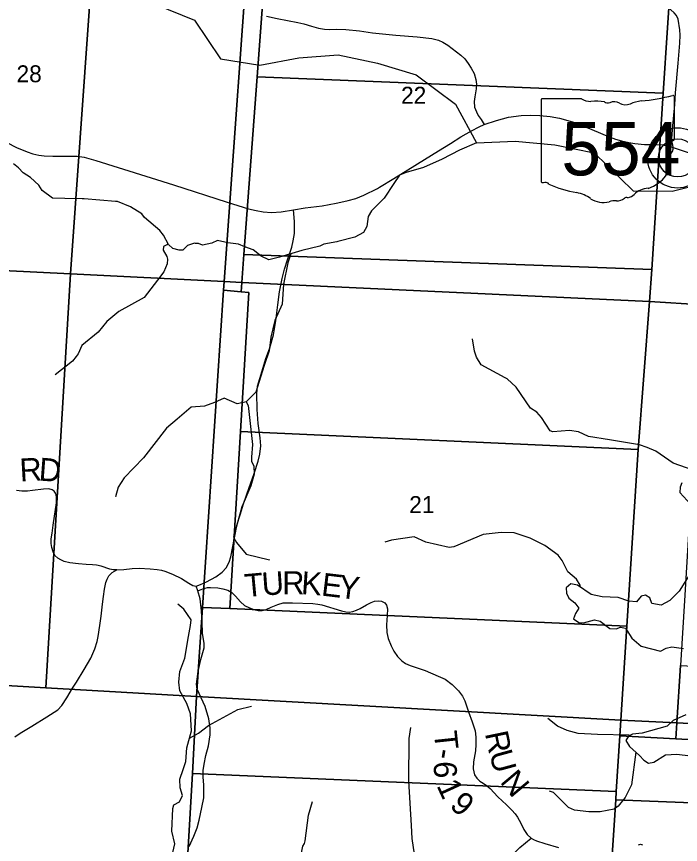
# Model space of a CAD drawing. Extents: x 1878108 to 2183446, y 146837 to 508383.
# Drawn here: x 2057947 to 2066610, y 348659 to 359472 of the extents above; entities that cross this region are included whole.
import ezdxf

# ---------------------------------------------------------------- set-up
doc = ezdxf.new("R2010")
doc.units = 0
for name, color, linetype in [('GM_X_County_Road', 7, 'Continuous'), ('GM_X_County_Road_Text', 7, 'Continuous'), ('GM_X_Major_Lake', 7, 'Continuous'), ('GM_X_Minor_River', 7, 'Continuous'), ('GM_X_Section', 7, 'Continuous'), ('GM_X_Section_Text', 7, 'Continuous'), ('GM_X_State_Location', 7, 'Continuous'), ('GM_X_State_Route', 7, 'Continuous'), ('GM_X_State_Shield', 7, 'Continuous'), ('GM_X_Township_Road', 7, 'Continuous'), ('GM_X_Township_Road_Text', 7, 'Continuous'), ('GM_X_Unincorporated', 7, 'Continuous'), ('GM_X_Unincorporated_Location', 7, 'Continuous')]:
    doc.layers.add(name, color=color, linetype=linetype)

msp = doc.modelspace()

# ---------------------------------------------------------------- linework, layer by layer
at = {"layer": 'GM_X_County_Road'}
for points in [[(2061207, 359477), (2061347, 359447), (2061616, 359395), (2061694, 359378), (2061798, 359348), (2061886, 359322), (2061965, 359307), (2062026, 359301), (2062127, 359306), (2062245, 359305), (2062423, 359287), (2062593, 359260), (2062898, 359231), (2063176, 359207), (2063366, 359184), (2063455, 359163), (2063508, 359138), (2063576, 359097), (2063744, 358966), (2063797, 358919), (2063841, 358861), (2063881, 358798), (2063917, 358727), (2063941, 358651), (2063948, 358590), (2063944, 358530), (2063939, 358500)], [(2063939, 358500), (2063927, 358422), (2063920, 358362), (2063925, 358289), (2063947, 358228), (2063970, 358181), (2064009, 358127), (2064051, 358062)], [(2060289, 352033), (2060349, 352056), (2060426, 352091), (2060548, 352155), (2060632, 352217), (2060683, 352274), (2060720, 352344), (2060745, 352417), (2060790, 352662), (2060824, 352842), (2060863, 352965), (2060910, 353106), (2060981, 353320), (2061046, 353506), (2061098, 353665), (2061122, 353758), (2061133, 353864), (2061126, 353968), (2061100, 354158), (2061087, 354338), (2061083, 354549), (2061090, 354645), (2061150, 354846), (2061201, 355007), (2061254, 355144), (2061300, 355317), (2061331, 355496), (2061355, 355705), (2061380, 355875), (2061414, 356051), (2061444, 356175), (2061487, 356310), (2061540, 356460), (2061558, 356543), (2061572, 356637), (2061573, 356796), (2061562, 356946)], [(2059257, 352245), (2059209, 352247), (2059162, 352254), (2059052, 352293), (2058991, 352307), (2058940, 352312), (2058855, 352315), (2058755, 352324), (2058640, 352339), (2058570, 352353), (2058524, 352376), (2058485, 352398), (2058448, 352434), (2058423, 352481), (2058406, 352538), (2058400, 352589), (2058398, 352652), (2058410, 352725), (2058425, 352829), (2058468, 353122), (2058468, 353195), (2058463, 353224), (2058455, 353249), (2058437, 353274), (2058413, 353292), (2058368, 353304), (2058297, 353299), (2058157, 353280), (2058088, 353274), (2058014, 353275), (2057945, 353281)], [(2057926, 350067), (2057992, 350112), (2058146, 350203), (2058340, 350324), (2058486, 350419), (2058538, 350472), (2058603, 350576), (2058677, 350699), (2058727, 350781), (2058828, 350945), (2058915, 351091), (2058969, 351214), (2058998, 351310), (2059011, 351377), (2059034, 351519), (2059050, 351643), (2059068, 351797), (2059082, 351896), (2059095, 351994), (2059112, 352082), (2059128, 352125), (2059150, 352167), (2059195, 352212), (2059257, 352245), (2059346, 352252), (2059455, 352265), (2059548, 352266), (2059690, 352259), (2059782, 352249), (2059838, 352241), (2059880, 352230), (2059981, 352191), (2060101, 352132), (2060197, 352072), (2060249, 352042), (2060289, 352033)], [(2060198, 348631), (2060260, 348767), (2060302, 348875), (2060330, 348978), (2060364, 349141), (2060389, 349267), (2060392, 349346), (2060391, 349434), (2060381, 349543), (2060380, 349627), (2060395, 349708), (2060417, 349819), (2060451, 349946), (2060473, 350091), (2060475, 350184), (2060456, 350298), (2060408, 350460), (2060356, 350576), (2060302, 350689), (2060295, 350752), (2060317, 350917), (2060351, 351076), (2060395, 351227), (2060397, 351286), (2060375, 351420), (2060371, 351568), (2060359, 351711), (2060344, 351869), (2060311, 351970), (2060289, 352033)]]:
    msp.add_lwpolyline(points, dxfattribs=at)
at = {"layer": 'GM_X_Major_Lake'}
for points in [[(2066628, 353383), (2066605, 353326), (2066602, 353256), (2066794, 353045)], [(2066778, 352260), (2066594, 351968), (2066474, 351846), (2066361, 351786), (2066236, 351806), (2066209, 351881), (2066154, 351915), (2066100, 351902), (2066035, 351830), (2065935, 351835), (2065799, 351883), (2065587, 351893), (2065444, 351923), (2065269, 352045), (2065181, 352065), (2065119, 352010), (2065124, 351940), (2065156, 351878), (2065233, 351815), (2065286, 351746), (2065239, 351675), (2065216, 351606), (2065285, 351559), (2065345, 351554), (2065491, 351595), (2065564, 351574), (2065691, 351480), (2065772, 351477), (2065826, 351496), (2065894, 351483), (2065978, 351354), (2066098, 351248), (2066352, 351182), (2066422, 351223), (2066498, 351240), (2066649, 351219)], [(2066193, 349719), (2066263, 349736), (2066414, 349830), (2066562, 349837), (2066741, 349816), (2066795, 349839), (2066873, 349970), (2066810, 350017), (2066744, 350038), (2066771, 350097), (2066980, 350165), (2067119, 350177), (2067178, 350202), (2067405, 350477)], [(2066681, 350352), (2066515, 350279), (2066438, 350206), (2066111, 350112), (2065984, 350098), (2065931, 350073), (2065899, 350019), (2065945, 349937), (2066075, 349823), (2066132, 349758), (2066193, 349719)]]:
    msp.add_lwpolyline(points, dxfattribs=at)
at = {"layer": 'GM_X_Minor_River'}
for points in [[(2059764, 359629), (2060267, 359426), (2060609, 358922), (2061120, 358838), (2061630, 358931), (2062144, 358971), (2062658, 358865), (2063161, 358712), (2063677, 358329), (2063951, 357825), (2064452, 357843), (2064970, 357798), (2065483, 357694), (2065993, 357194), (2066503, 357190), (2067005, 357320)], [(2063951, 357825), (2063727, 357726), (2063500, 357611), (2063257, 357500), (2063033, 357436), (2062944, 357400), (2062870, 357291), (2062745, 357100), (2062579, 356933), (2062535, 356861), (2062520, 356730), (2062474, 356650), (2062363, 356589), (2062139, 356534), (2062125, 356530), (2061956, 356501), (2061906, 356475), (2061668, 356416), (2061377, 356328), (2061238, 356295), (2061139, 356343), (2061035, 356426), (2060927, 356464), (2060845, 356500), (2060705, 356519), (2060567, 356546), (2060496, 356512), (2060372, 356485), (2060322, 356509), (2060284, 356509), (2060268, 356511), (2060176, 356484), (2060116, 356420), (2060069, 356420), (2059985, 356441), (2059928, 356497), (2059864, 356619), (2059818, 356679), (2059615, 356846), (2059581, 356894), (2059433, 356986), (2059266, 357057), (2059239, 357055), (2058831, 357091), (2058803, 357091), (2058579, 357094), (2058415, 357101), (2058283, 357199), (2058239, 357269), (2058127, 357370), (2058034, 357430), (2057972, 357498), (2057908, 357548)], [(2059923, 356507), (2059910, 356489), (2059866, 356471), (2059860, 356423), (2059908, 356340), (2059918, 356302), (2059911, 356242), (2059867, 356140), (2059786, 356030), (2059613, 355805), (2059280, 355622), (2059125, 355488), (2059014, 355348), (2058799, 355176), (2058749, 355066), (2058726, 355034), (2058676, 354972), (2058449, 354792)], [(2061528, 356373), (2061488, 356257), (2061431, 355978), (2061412, 355717), (2061316, 355502), (2061263, 355286), (2061245, 355107), (2061178, 354913), (2061070, 354568), (2060945, 354442), (2060969, 354391), (2061025, 353883), (2061013, 353716), (2061012, 353664), (2061044, 353600), (2061046, 353495), (2061005, 353345), (2060902, 353108), (2060888, 353070), (2060780, 352673), (2060818, 352603), (2060945, 352452), (2061249, 352376), (2061249, 352382)], [(2066776, 353548), (2066517, 353639), (2066291, 353795), (2066177, 353844), (2066075, 353878), (2065683, 353944), (2065409, 353986), (2065281, 354050), (2065161, 354067), (2064944, 354050), (2064910, 354060), (2064799, 354237), (2064737, 354306), (2064655, 354359), (2064468, 354633), (2064350, 354742), (2064324, 354754), (2064012, 354922), (2063949, 355025), (2063923, 355103), (2063898, 355262)], [(2060947, 354439), (2060825, 354414), (2060657, 354487), (2060529, 354430), (2060400, 354384), (2060226, 354369), (2060041, 354213), (2059904, 354095), (2059602, 353707), (2059351, 353447), (2059274, 353325), (2059240, 353200), (2059238, 353199)], [(2065308, 352018), (2065303, 352044), (2065252, 352126), (2065141, 352219), (2065069, 352370), (2065016, 352438), (2064840, 352562), (2064649, 352658), (2064440, 352728), (2064269, 352734), (2064035, 352707), (2063654, 352547), (2063594, 352536), (2063287, 352606), (2063134, 352677), (2062838, 352635), (2062752, 352608)], [(2059985, 348554), (2060012, 348666), (2059972, 348831), (2059988, 349130), (2060000, 349175), (2060074, 349218), (2060113, 349297), (2060081, 349399), (2060077, 349512), (2060120, 349638), (2060157, 349744), (2060169, 349923), (2060230, 350145), (2060215, 350366), (2060168, 350501), (2060076, 350664), (2060063, 350781), (2060077, 350919), (2060142, 351092), (2060191, 351377), (2060218, 351517), (2060224, 351591), (2060129, 351732), (2060051, 351796)], [(2060203, 350046), (2060322, 350111), (2060451, 350211), (2060835, 350424), (2061015, 350464)], [(2065942, 350086), (2065529, 350094), (2065274, 350107), (2065132, 350146), (2065008, 350205), (2064881, 350304)], [(2063089, 350187), (2063068, 350042), (2063060, 349490), (2063098, 348905), (2063105, 348737), (2063136, 348534), (2063120, 348431), (2063127, 348353), (2063217, 348252), (2063354, 347966), (2063408, 347826), (2063436, 347534), (2063536, 347297), (2063572, 347071)], [(2066030, 349863), (2065971, 349436), (2065888, 349272), (2065799, 349158), (2065745, 349120), (2065562, 349085), (2065414, 349084), (2065226, 349106), (2065148, 349141), (2064952, 349339), (2064900, 349357)], [(2060851, 346403), (2060918, 346514), (2060942, 346518), (2061081, 346628), (2061198, 346938), (2061229, 346996), (2061337, 347088), (2061484, 347304), (2061533, 347463), (2061629, 347804), (2061669, 347896), (2061712, 348107), (2061717, 348265), (2061658, 348504), (2061684, 348639), (2061704, 348673), (2061715, 348705), (2061758, 349042), (2061811, 349219)]]:
    msp.add_lwpolyline(points, dxfattribs=at)
at = {"layer": 'GM_X_Section'}
for points in [[(2056839, 361514), (2059023, 361383), (2058653, 356110), (2056451, 356219)], [(2059023, 361383), (2061031, 361263), (2061016, 361049), (2060656, 356011), (2058653, 356110)], [(2061262, 361039), (2061086, 358686), (2060912, 356364), (2060885, 356000), (2060656, 356011), (2061016, 361049)], [(2066553, 361036), (2066386, 358472), (2061086, 358686), (2061262, 361039), (2065125, 360885), (2065143, 361100)], [(2067527, 360995), (2069735, 360902), (2072035, 360805), (2071684, 355405), (2066899, 355705), (2066208, 355752), (2066235, 356167), (2066386, 358472), (2066553, 361036)], [(2066386, 358472), (2066235, 356167), (2060912, 356364), (2061086, 358686)], [(2066235, 356167), (2066208, 355752), (2060885, 356000), (2060912, 356364)], [(2058653, 356110), (2058328, 350705), (2056101, 350834), (2056451, 356219)], [(2060656, 356011), (2060649, 355898), (2060375, 351756), (2060297, 350591), (2058328, 350705), (2058653, 356110)], [(2060885, 356000), (2060876, 355877), (2060649, 355898), (2060656, 356011)], [(2060885, 356000), (2066208, 355752), (2066057, 353818), (2060870, 354052), (2060978, 355868), (2060876, 355877)], [(2060649, 355898), (2060876, 355877), (2060978, 355868), (2060870, 354052), (2060731, 351740), (2060375, 351756)], [(2066208, 355752), (2066899, 355705), (2066838, 354726), (2066779, 353795), (2066724, 352860), (2066668, 351913), (2066613, 350998), (2066564, 350246), (2065833, 350284), (2065911, 351510), (2066057, 353818)], [(2060870, 354052), (2066057, 353818), (2065911, 351510), (2060731, 351740)], [(2060375, 351756), (2060731, 351740), (2065911, 351510), (2065833, 350284), (2060297, 350591)], [(2066613, 350998), (2071383, 350739), (2071345, 349999), (2066564, 350246)], [(2054872, 350905), (2056101, 350834), (2058328, 350705), (2060297, 350591), (2060244, 349584), (2060117, 347430), (2059969, 345275), (2054518, 345558)], [(2060297, 350591), (2065833, 350284), (2065820, 350078), (2065773, 349349), (2060244, 349584)], [(2065833, 350284), (2066564, 350246), (2066550, 350038), (2065820, 350078)], [(2066564, 350246), (2071345, 349999), (2071331, 349777), (2066550, 350038)], [(2065820, 350078), (2066550, 350038), (2071331, 349777), (2071283, 349025), (2065767, 349241), (2065773, 349349)], [(2065767, 349241), (2065712, 348386), (2065657, 347513), (2065633, 347139), (2060117, 347430), (2060244, 349584), (2065773, 349349)], [(2065767, 349241), (2071283, 349025), (2071227, 348141), (2065712, 348386)]]:
    msp.add_lwpolyline(points, close=True, dxfattribs=at)
at = {"layer": 'GM_X_State_Route'}
for points in [[(2062683, 357244), (2062871, 357358), (2063452, 357718), (2063610, 357816), (2063746, 357901), (2063882, 357981), (2063983, 358032), (2064051, 358062), (2064208, 358116), (2064368, 358157), (2064531, 358179), (2064656, 358185), (2064777, 358182), (2064910, 358167), (2065031, 358145), (2065200, 358099), (2065400, 358021), (2065453, 357998)], [(2065453, 357998), (2065682, 357902), (2065761, 357872), (2065840, 357847), (2065938, 357827), (2066017, 357814), (2066140, 357802), (2066281, 357799), (2066381, 357795), (2066489, 357770), (2066827, 357658)], [(2057691, 357891), (2057948, 357763), (2058087, 357704), (2058160, 357681), (2058236, 357662), (2058309, 357652), (2058420, 357647), (2058630, 357649), (2058736, 357649), (2058830, 357635), (2058982, 357592), (2059994, 357273), (2060695, 357049), (2060975, 356962), (2061074, 356938), (2061164, 356920), (2061275, 356913), (2061401, 356923), (2061562, 356946), (2061713, 356973), (2061933, 357002), (2062118, 357036), (2062139, 357041)], [(2062139, 357041), (2062275, 357069), (2062373, 357096), (2062479, 357138), (2062656, 357227), (2062683, 357244)]]:
    msp.add_lwpolyline(points, dxfattribs=at)
at = {"layer": 'GM_X_State_Shield'}
for p, q in [((2064791, 358380), (2064791, 357323)), ((2065318, 358398), (2064808, 358398)), ((2066531, 357871), (2066531, 358424)), ((2066531, 357872), (2066531, 357871))]:
    msp.add_line(p, q, dxfattribs=at)
for centre, major_axis, start_param, end_param in [((2064811, 358382), (20.2, 0), 1.712693, 3.28349), ((2065439, 358521), (196, 0), 4.042523, 4.731795), ((2065504, 357805), (702, 0), 1.404758, 1.657858), ((2065663, 358388), (56.4, 0), 3.836095, 5.185415), ((2065746, 358265), (117, 0), 0.950623, 2.079405), ((2065897, 358433), (141, 0), 4.081561, 5.145723), ((2066146, 358075), (371, 0), 1.699011, 2.107814), ((2065911, 359839), (1845, 0), 4.814394, 5.042369), ((2066512, 358427), (19.4, 0), 6.141152, 7.989035), ((2066527, 357831), (30, 0), 1.883978, 3.671073), ((2066336, 357761), (180, 0), 5.934695, 6.695948), ((2066510, 357869), (20.7, 0), 5.05454, 6.418171), ((2066600, 357640), (131, 0), 2.387724, 3.262537), ((2066014, 357570), (462, 0), 5.101752, 6.440018), ((2064811, 357321), (20.3, 0), 3.00124, 4.508301), ((2064814, 357429), (155, 0), 4.665946, 4.897461), ((2064846, 357262), (56, 0), 0.519207, 1.627899), ((2065552, 358212), (1333, 0), 4.195997, 4.488961), ((2065155, 356849), (417, 0), 0.823519, 1.323587), ((2065889, 357221), (149, 0), 4.937069, 5.64225), ((2066209, 357027), (253, 0), 1.647645, 2.488434), ((2065606, 357257), (265, 0), 4.026481, 4.996735), ((2065759, 356892), (217, 0), 1.495662, 1.94098), ((2065778, 357178), (141, 0), 4.691044, 5.507374), ((2065906, 357076), (39.7, 0), 1.147584, 2.315152)]:
    msp.add_ellipse(centre, major_axis=major_axis, ratio=0.8, start_param=start_param, end_param=end_param, dxfattribs=at)
at = {"layer": 'GM_X_Township_Road'}
for points in [[(2066489, 357770), (2066511, 358046), (2066536, 358322), (2066548, 358475), (2066582, 358863), (2066602, 359124), (2066607, 359229), (2066602, 359298), (2066579, 359438), (2066558, 359485), (2066530, 359521), (2066448, 359594), (2066416, 359629), (2066374, 359704), (2066335, 359776), (2066302, 359839), (2066265, 359902), (2066227, 359970), (2066228, 360019), (2066234, 360057)], [(2060311, 351970), (2060376, 351998), (2060439, 352014), (2060476, 352015), (2060573, 352009), (2060640, 351999), (2060705, 351980), (2060757, 351949), (2060802, 351901), (2060868, 351828), (2060920, 351781), (2060985, 351748), (2061044, 351726), (2061098, 351716), (2061152, 351716), (2061206, 351728), (2061268, 351757), (2061356, 351794), (2061426, 351814), (2061547, 351816), (2061813, 351806), (2061879, 351798), (2061932, 351790), (2062187, 351711), (2062245, 351697), (2062289, 351695), (2062334, 351702), (2062382, 351719), (2062431, 351743), (2062513, 351787), (2062576, 351821), (2062620, 351836), (2062664, 351843), (2062708, 351835), (2062752, 351816), (2062775, 351785), (2062786, 351735), (2062782, 351651), (2062774, 351528), (2062779, 351429), (2062796, 351351), (2062835, 351255), (2062871, 351185), (2062917, 351116), (2062973, 351056), (2063021, 351021), (2063083, 350996), (2063160, 350971), (2063280, 350930), (2063450, 350859), (2063539, 350816), (2063631, 350748), (2063713, 350666), (2063766, 350594), (2063795, 350536), (2063845, 350393), (2063894, 350262), (2063930, 350145), (2063940, 350060), (2063941, 349964), (2063938, 349883), (2063910, 349740), (2063907, 349647), (2063924, 349567), (2063952, 349525), (2063991, 349486), (2064035, 349460), (2064080, 349429), (2064128, 349389), (2064229, 349280), (2064339, 349177), (2064411, 349107), (2064455, 349059), (2064485, 349015), (2064526, 348936), (2064566, 348855), (2064611, 348790), (2064661, 348742), (2064693, 348722), (2064734, 348706), (2064839, 348673), (2065017, 348619)], [(2064272, 348243), (2064249, 348303), (2064248, 348366), (2064261, 348404), (2064292, 348437), (2064361, 348477), (2064426, 348526), (2064440, 348545), (2064516, 348621), (2064661, 348742)], [(2066062, 348656), (2066090, 348661), (2066117, 348656)]]:
    msp.add_lwpolyline(points, dxfattribs=at)
at = {"layer": 'GM_X_Unincorporated'}
for radius in [393, 249]:
    msp.add_circle((2066573, 357626), radius, dxfattribs=at)
at = {"layer": 'GM_X_Unincorporated_Location'}
msp.add_line((2066573, 357626), (2066573, 357626), dxfattribs=at)

# ---------------------------------------------------------------- texts
at = {"layer": 'GM_X_County_Road_Text'}
for s, rotation, p in [('R', 3.3115, (2057995, 353398)), ('D', 355.6901, (2058230, 353413))]:
    msp.add_text(s, height=300, rotation=rotation, dxfattribs=at).set_placement(p)
at = {"layer": 'GM_X_Section_Text'}
for s, p in [('28', (2057947, 358614)), ('22', (2062965, 358334)), ('21', (2063071, 352988))]:
    msp.add_text(s, height=221, rotation=0, dxfattribs=at).set_placement(p)
at = {"layer": 'GM_X_State_Location'}
msp.add_text('554', height=1, rotation=0, dxfattribs=at).set_placement((2065288, 357709))
for s in ['s', 'r']:
    msp.add_text(s, height=1, dxfattribs=at).set_placement((2065641, 357781))
at = {"layer": 'GM_X_State_Shield'}
msp.add_text('554', height=696.1, dxfattribs=at).set_placement((2065056, 357398))
at = {"layer": 'GM_X_Township_Road_Text'}
for s, rotation, p in [('T', 5.227, (2060935, 351889)), ('U', 4.1492, (2061157, 351909)), ('R', 359.9532, (2061414, 351928)), ('K', 356.2417, (2061655, 351928)), ('E', 353.1955, (2061915, 351911)), ('Y', 352.823, (2062137, 351885)), ('T', 276.0283, (2063392, 350128)), ('R', 281.7524, (2064058, 350110)), ('-', 260.5826, (2063416, 349926)), ('U', 285.2845, (2064112, 349850)), ('6', 271.0781, (2063391, 349744)), ('N', 310.0345, (2064246, 349473)), ('1', 294.5662, (2063424, 349430)), ('9', 319.2114, (2063585, 349150))]:
    msp.add_text(s, height=300, rotation=rotation, dxfattribs=at).set_placement(p)

doc.saveas('drawing.dxf')
